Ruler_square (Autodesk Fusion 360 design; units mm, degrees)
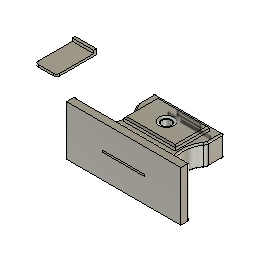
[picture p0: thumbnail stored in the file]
part number: 2025-10-15-13-13-53-256
sketch "Sketch1" plane through (0, 0, 0) normal (0, 0, 1) x axis (1, 0, 0)
  line L1 (24.25, 20) -> (-24.25, 20)
  line L2 (24.25, -20) -> (24.25, 20)
  line L3 (-24.25, -20) -> (24.25, -20)
  line L4 (-24.25, 20) -> (-24.25, -20)
  point P1 (0, 0)
  point P6 (0, 0)
  point P2 (-24.25, 20)
  point P3 (24.25, 20)
  point P5 (-24.25, -20)
  horizontal L1
  vertical L2
  horizontal L3
  vertical L4
  coincident P1 P6
  dimension "d1" distance P2 P3 = 48.5
  dimension "d2" distance P2 P5 = 40
  dimension "d3" distance L2 P6 = 24.25
  dimension "d4" distance P1 L3 = 20
extrude "Extrude1" new body sketch "Sketch1" along normal blind 15
sketch "Sketch2" plane through (0, -20, 0) normal (0, -1, 0) x axis (1, 0, 0)
  line L1 (24.25, 0) -> (-24.25, 0)
  line L2 (24.25, 15) -> (24.25, 0)
  line L3 (-24.25, 15) -> (24.25, 15)
  line L4 (-24.25, 0) -> (-24.25, 15)
  line L5 (40, 25) -> (-40, 25)
  line L6 (40, -10) -> (40, 25)
  line L7 (-40, -10) -> (40, -10)
  line L8 (-40, 25) -> (-40, -10)
  point P6 (-40, 25)
  point P7 (40, 25)
  point P9 (-40, -10)
  horizontal L5
  vertical L6
  horizontal L7
  vertical L8
  dimension "d7" distance P6 P7 = 80
  dimension "d8" distance P6 P9 = 35
  dimension "d9" distance L2 L6 = 15.75
  dimension "d10" distance L1 L7 = 10
extrude "Extrude2" add sketch "Sketch2" along normal blind 6
sketch "Sketch3" plane through (0, 20, 0) normal (0, 1, 0) x axis (-1, 0, 0)
  line L1 (24.25, 0) -> (-24.25, 0)
  line L2 (24.25, 15) -> (24.25, 0)
  line L3 (-24.25, 15) -> (24.25, 15)
  line L4 (-24.25, 0) -> (-24.25, 15)
  line L5 (-14.6, 6.85) -> (14.6, 6.85)
  line L6 (-14.6, 8.15) -> (-14.6, 6.85)
  line L7 (14.6, 8.15) -> (-14.6, 8.15)
  line L8 (14.6, 6.85) -> (14.6, 8.15)
  line L9 (8, 6.85) -> (-8, 6.85)
  line L10 (8.2, 10.15) -> (-7.8, 10.15)
  line L11 (8.2, 8.15) -> (8.2, 10.15)
  line L12 (-7.8, 8.15) -> (8.2, 8.15)
  line L13 (-7.8, 10.15) -> (-7.8, 8.15)
  line L14 (-7.8, 10.15) -> (8.2, 10.15)
  line L15 (-7.8, 12.15) -> (-7.8, 10.15)
  line L16 (8.2, 12.15) -> (-7.8, 12.15)
  line L17 (8.2, 10.15) -> (8.2, 12.15)
  point P10 (-8, 6.85)
  point P6 (14.6, 6.85)
  point P7 (-14.6, 6.85)
  point P9 (14.6, 8.15)
  point P8 (-14.6, 8.15)
  point P12 (-7.8, 10.15)
  point P13 (8.2, 10.15)
  point P15 (-7.8, 8.15)
  point P16 (-7.8, 10.15)
  point P18 (8.2, 12.15)
  horizontal L5
  vertical L6
  horizontal L7
  vertical L8
  horizontal L9
  coincident L5 P10
  horizontal L10
  vertical L11
  horizontal L12
  vertical L13
  horizontal L14
  vertical L15
  horizontal L16
  vertical L17
  dimension "d13" distance P6 P7 = 29.2
  dimension "d14" distance P6 P9 = 1.3
  dimension "d15" distance L4 P8 = 9.65
  dimension "d16" distance L3 L7 = 6.85
  dimension "d41" distance P12 P13 = 16
  dimension "d42" distance P12 P15 = 2
  dimension "d43" distance L8 L11 = 6.4
  dimension "d44" distance L7 L10 = 2
  dimension "d79" distance P13 P16 = 16
  dimension "d80" distance P13 P18 = 2
extrude "Extrude3" cut sketch "Sketch3" profile of L5 L6 L7 L8 L9 L12 against normal blind 50
fillet "Fillet1" radius 4
sketch "Sketch4" plane through (0, 0, 15) normal (0, 0, 1) x axis (-1, 0, 0)
  line L1 (24.25, 16) -> (24.25, -20)
  line L2 (-24.25, 16) -> (24.25, 16)
  line L3 (-24.25, -20) -> (-24.25, 16)
  line L4 (24.25, -20) -> (-24.25, -20)
  circle C1 centre (38, 4) radius 18
  circle C2 centre (-38, 4) radius 18
  dimension "d23" diameter C1 = 36
  dimension "d24" diameter C2 = 36
extrude "Extrude4" cut sketch "Sketch4" profile of L1 L3 C1 C2 against normal blind 15
fillet "Fillet3" radius 4
fillet "Fillet4" radius 1
fillet "Fillet5" radius 1
sketch "Sketch5" plane through (0, 0, 15) normal (0, 0, 1) x axis (-1, 0, 0)
  line L1 (-23.25, -20) -> (-23.25, -8.9976)
  line L2 (23.25, -8.9976) -> (23.25, -20)
  line L3 (-23.1168, 16) -> (23.25, 16)
  line L4 (-18, -16) -> (18, -16)
  line L5 (-18, 8) -> (-18, -16)
  line L6 (18, 8) -> (-18, 8)
  line L7 (18, -16) -> (18, 8)
  line L8 (23.25, -20) -> (-23.25, -20)
  line L9 (23.25, 16) -> (23.25, 15.9765)
  arc A1 centre (20.25, -8.9976) radius 3 clockwise from (22.6705, -7.2252) to (23.25, -8.9976)
  arc A2 centre (38, 4) radius 19 clockwise from (22.6705, -7.2252) to (23.25, 15.9765)
  arc A3 centre (-38, 4) radius 19 clockwise from (-22.7362, 15.3144) to (-22.6705, -7.2252)
  arc A4 centre (-20.3261, 17.1009) radius 3 clockwise from (-22.7362, 15.3144) to (-23.1168, 16)
  arc A5 centre (-20.25, -8.9976) radius 3 clockwise from (-23.25, -8.9976) to (-22.6705, -7.2252)
  point P17 (-18, 8)
  point P18 (18, 8)
  horizontal L4
  vertical L5
  horizontal L6
  vertical L7
  dimension "d68" distance P17 P18 = 36
  dimension "d69" distance L4 L6 = 24
  dimension "d70" distance L3 L6 = 8
extrude "Extrude5" add sketch "Sketch5" profile of L4 L5 L6 L7 along normal blind 3
extrude "Extrude7" cut sketch "Sketch3" profile of L7 L10 L11 L12 L13 against normal blind 30
sketch "Sketch6" plane through (0, 0, 18) normal (0, 0, 1) x axis (-1, 0, 0)
  line L1 (-18, 8) -> (18, 8)
  line L2 (-18, -16) -> (-18, 8)
  line L3 (18, -16) -> (-18, -16)
  line L4 (18, 8) -> (18, -16)
  circle C1 centre (0, -4) radius 3.2
  dimension "d49" diameter C1 = 6.4
extrude "Extrude8" cut sketch "Sketch6" profile of C1 against normal blind 12
fillet "Fillet7" radius 1
chamfer "Chamfer3" distance 1
chamfer "Chamfer4" distance 1
extrude "Extrude12" cut sketch "Sketch3" profile of L10 L14 L15 L16 L17 against normal blind 2
fillet "Fillet10" radius 1
sketch "Sketch10" plane through (0, 0, 18) normal (0, 0, 1) x axis (-1, 0, 0)
  line L1 (65, -20) -> (80, -20)
  line L2 (65, 8) -> (65, -20)
  line L3 (80, 8) -> (65, 8)
  line L4 (80, -20) -> (80, 8)
  line L5 (17, -15) -> (-17, -15)
  line L6 (17, 7) -> (17, -15)
  line L7 (-17, 7) -> (17, 7)
  line L8 (-17, -15) -> (-17, 7)
  circle C1 centre (0, -4) radius 5.2
  point P2 (80, -20)
  point P3 (65, -20)
  point P5 (80, 8)
  horizontal L1
  vertical L2
  horizontal L3
  vertical L4
  dimension "d85" distance P2 P3 = 15
  dimension "d86" distance P2 P5 = 28
extrude "Extrude13" new body sketch "Sketch10" profile of L1 L2 L3 L4 along normal blind 1.6
sketch "Sketch11" plane through (0, 0, 19.6) normal (0, 0, 1) x axis (-1, 0, 0)
  line L1 (65, 8) -> (80, 8)
  line L2 (65, -20) -> (65, 8)
  line L3 (80, -20) -> (65, -20)
  line L4 (80, 8) -> (80, -20)
  line L5 (65, -20) -> (80, -20)
  line L6 (65, -18) -> (65, -20)
  line L7 (80, -18) -> (65, -18)
  line L8 (80, -20) -> (80, -18)
  point P5 (80, -20)
  point P6 (80, -20)
  point P9 (80, -18)
  horizontal L5
  vertical L6
  horizontal L7
  vertical L8
  coincident P5 P6
  dimension "d89" distance P6 P9 = 2
extrude "Extrude14" add sketch "Sketch11" profile of L2 L3 L4 L5 L6 L7 L8 along normal blind 2
fillet "Fillet11" radius 2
